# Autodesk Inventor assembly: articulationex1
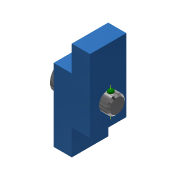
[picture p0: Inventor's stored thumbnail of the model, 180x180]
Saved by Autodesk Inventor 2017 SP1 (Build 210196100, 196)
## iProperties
Created: 2006-05
Part Number: articulationex1
Document SubType Name: Assembly
Designer: Administrateur
Manufacturer: Standard
Standards Organization: Custom
Author: Administrateur
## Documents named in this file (4)
- H:\Consmec\TSsi\02-Cours\02-03-RDM\02-03-02-Cisaillement\02-03-02-02-Exercices Cisaillement\03-03-02-02-01-Exercice Cisaillement 1\03-03-02-02-01-02-Dessin exercices cisaillement\articulationex1.iam
- H:\Consmec\TSsi\02-Cours\02-03-RDM\02-03-02-Cisaillement\02-03-02-02-Exercices Cisaillement\03-03-02-02-01-Exercice Cisaillement 1\03-03-02-02-01-02-Dessin exercices cisaillement\axeex1.ipt
- H:\Consmec\TSsi\02-Cours\02-03-RDM\02-03-02-Cisaillement\02-03-02-02-Exercices Cisaillement\03-03-02-02-01-Exercice Cisaillement 1\03-03-02-02-01-02-Dessin exercices cisaillement\goupilleex1.ipt
- H:\Consmec\TSsi\02-Cours\02-03-RDM\02-03-02-Cisaillement\02-03-02-02-Exercices Cisaillement\03-03-02-02-01-Exercice Cisaillement 1\03-03-02-02-01-02-Dessin exercices cisaillement\plaqueex1.ipt
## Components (4 placed, 3 different names)
1. axeex1:1 — Logement:1, Plaquer:1, Tangente:1, Orientation:2, Affleurer:1
2. goupilleex1:1 — Plaquer:2, Tangente:1, Affleurer:1, Orientation:3
3. plaqueex1:1 — Logement:1, Logement:2, Orientation:1, Orientation:3
4. plaqueex1:2 — Logement:2, Orientation:1
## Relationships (9: Angle 3, Insert 2, Mate 2, Tangent 1, Flush 1)
- Logement:1 [Insert]: axeex1:1 ↔ plaqueex1:1
- Logement:2 [Insert]: plaqueex1:1 ↔ plaqueex1:2
- Orientation:1 [Angle]: plaqueex1:1 ↔ plaqueex1:2
- Plaquer:1 [Mate]: axeex1:1
- Plaquer:2 [Mate]: goupilleex1:1
- Tangente:1: axeex1:1 ↔ goupilleex1:1
- Orientation:2 [Angle]: axeex1:1
- Affleurer:1 [Flush]: axeex1:1 ↔ goupilleex1:1
- Orientation:3 [Angle]: goupilleex1:1 ↔ plaqueex1:1
## Named parameters: sa_0 = 0, sa_1 = 0 mm, sa_2 = 5e+07 mm, sa_3 = 0, sa_4 = 0 mm, sa_5 = -5e+07 mm
